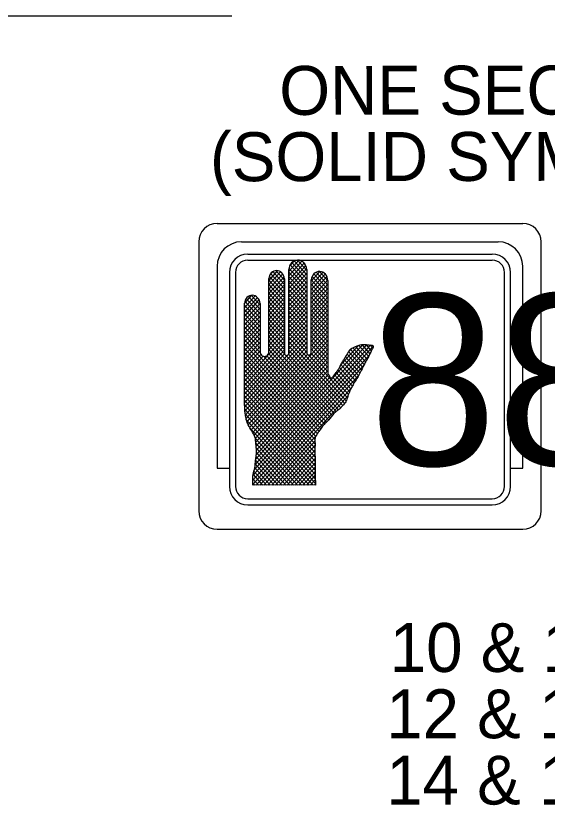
# Model space of a CAD drawing. Extents: x 1280742 to 1281742, y 1892348 to 1892988.
# Drawn here: x 1281004.7 to 1281048.2, y 1892503.7 to 1892568.2 of the extents above; entities that cross this region are included whole.
import ezdxf

# ---------------------------------------------------------------- set-up
doc = ezdxf.new("R2010")
doc.units = 0
doc.layers.add('T_Drafting', color=7, linetype='Continuous')
doc.layers.add('T_Notes', color=7, linetype='Continuous')

msp = doc.modelspace()

# ---------------------------------------------------------------- linework, layer by layer
at = {"layer": 'T_Drafting'}
for p, q in [((1281021.202, 1892551.259), (1281046.202, 1892551.259)), ((1281019.702, 1892549.759), (1281019.702, 1892527.759)), ((1281023.202, 1892549.759), (1281044.202, 1892549.759)), ((1281047.702, 1892527.759), (1281047.702, 1892549.759)), ((1281023.702, 1892548.759), (1281043.702, 1892548.759)), ((1281023.702, 1892548.259), (1281043.702, 1892548.259)), ((1281027.066, 1892547.343), (1281027.888, 1892548.256)), ((1281027.066, 1892546.99), (1281028.131, 1892548.173)), ((1281027.067, 1892546.637), (1281028.315, 1892548.024)), ((1281027.067, 1892546.283), (1281028.45, 1892547.82)), ((1281027.119, 1892547.756), (1281027.52, 1892548.202)), ((1281027.171, 1892547.871), (1281028.53, 1892546.361)), ((1281027.317, 1892548.062), (1281028.53, 1892546.715)), ((1281027.513, 1892548.198), (1281028.53, 1892547.069)), ((1281027.774, 1892548.262), (1281028.529, 1892547.423)), ((1281028.24, 1892548.097), (1281028.382, 1892547.939)), ((1281021.202, 1892547.759), (1281021.202, 1892531.259)), ((1281022.202, 1892547.259), (1281022.202, 1892529.759)), ((1281022.702, 1892547.259), (1281022.702, 1892529.759)), ((1281025.428, 1892546.583), (1281026.165, 1892547.402)), ((1281025.428, 1892546.23), (1281026.397, 1892547.307)), ((1281025.428, 1892545.877), (1281026.565, 1892547.14)), ((1281025.485, 1892547), (1281025.796, 1892547.346)), ((1281025.58, 1892547.164), (1281026.701, 1892545.918)), ((1281025.755, 1892547.323), (1281026.701, 1892546.272)), ((1281025.997, 1892547.408), (1281026.701, 1892546.626)), ((1281026.422, 1892547.289), (1281026.591, 1892547.101)), ((1281027.073, 1892540.658), (1281027.065, 1892547.485)), ((1281027.066, 1892547.281), (1281028.531, 1892545.653)), ((1281027.067, 1892545.93), (1281028.525, 1892547.55)), ((1281027.068, 1892545.577), (1281028.529, 1892547.201)), ((1281027.081, 1892547.617), (1281028.531, 1892546.007)), ((1281028.529, 1892547.504), (1281028.537, 1892540.726)), ((1281028.896, 1892546.548), (1281029.602, 1892547.332)), ((1281028.896, 1892546.195), (1281029.859, 1892547.264)), ((1281028.897, 1892545.842), (1281030.048, 1892547.121)), ((1281029.111, 1892547.13), (1281030.258, 1892545.855)), ((1281029.303, 1892547.27), (1281030.257, 1892546.209)), ((1281029.565, 1892547.332), (1281030.257, 1892546.563)), ((1281044.702, 1892529.759), (1281044.702, 1892547.259)), ((1281045.202, 1892529.759), (1281045.202, 1892547.259)), ((1281046.202, 1892531.259), (1281046.202, 1892547.759)), ((1281025.434, 1892540.786), (1281025.427, 1892546.751)), ((1281025.427, 1892546.626), (1281026.702, 1892545.21)), ((1281025.429, 1892545.524), (1281026.674, 1892546.908)), ((1281025.429, 1892545.171), (1281026.701, 1892546.584)), ((1281025.463, 1892546.94), (1281026.702, 1892545.564)), ((1281026.7, 1892546.737), (1281026.707, 1892540.691)), ((1281027.066, 1892546.927), (1281028.531, 1892545.299)), ((1281027.067, 1892546.573), (1281028.532, 1892544.945)), ((1281027.068, 1892545.224), (1281028.53, 1892546.848)), ((1281027.069, 1892544.871), (1281028.53, 1892546.495)), ((1281028.903, 1892540.694), (1281028.896, 1892546.642)), ((1281028.897, 1892545.489), (1281030.183, 1892546.918)), ((1281028.897, 1892546.66), (1281030.258, 1892545.148)), ((1281028.898, 1892545.135), (1281030.254, 1892546.643)), ((1281028.973, 1892546.93), (1281030.258, 1892545.501)), ((1281030.257, 1892546.595), (1281030.266, 1892538.938)), ((1281025.428, 1892546.272), (1281026.703, 1892544.856)), ((1281025.428, 1892545.918), (1281026.703, 1892544.502)), ((1281025.43, 1892544.818), (1281026.701, 1892546.231)), ((1281025.43, 1892544.465), (1281026.702, 1892545.877)), ((1281027.067, 1892546.219), (1281028.532, 1892544.591)), ((1281027.067, 1892545.865), (1281028.533, 1892544.237)), ((1281027.069, 1892544.518), (1281028.531, 1892546.142)), ((1281028.896, 1892546.307), (1281030.259, 1892544.794)), ((1281028.897, 1892545.953), (1281030.259, 1892544.44)), ((1281028.898, 1892544.782), (1281030.257, 1892546.293)), ((1281028.898, 1892544.429), (1281030.258, 1892545.94)), ((1281023.439, 1892544.728), (1281024.035, 1892545.389)), ((1281023.44, 1892544.374), (1281024.31, 1892545.341)), ((1281023.44, 1892544.021), (1281024.506, 1892545.205)), ((1281023.759, 1892545.298), (1281024.713, 1892544.238)), ((1281023.998, 1892545.386), (1281024.713, 1892544.592)), ((1281024.402, 1892545.291), (1281024.624, 1892545.044)), ((1281025.429, 1892545.564), (1281026.703, 1892544.148)), ((1281025.429, 1892545.21), (1281026.704, 1892543.794)), ((1281025.43, 1892544.111), (1281026.702, 1892545.524)), ((1281027.068, 1892545.511), (1281028.533, 1892543.883)), ((1281027.069, 1892544.165), (1281028.531, 1892545.789)), ((1281027.07, 1892543.812), (1281028.531, 1892545.436)), ((1281028.897, 1892545.599), (1281030.26, 1892544.086)), ((1281028.897, 1892545.245), (1281030.26, 1892543.732)), ((1281028.899, 1892544.076), (1281030.258, 1892545.586)), ((1281028.899, 1892543.723), (1281030.258, 1892545.233)), ((1281023.448, 1892536.487), (1281023.439, 1892544.73)), ((1281023.439, 1892544.592), (1281024.714, 1892543.176)), ((1281023.44, 1892543.668), (1281024.643, 1892545.005)), ((1281023.441, 1892543.315), (1281024.712, 1892544.727)), ((1281023.472, 1892544.91), (1281024.714, 1892543.53)), ((1281023.586, 1892545.137), (1281024.713, 1892543.884)), ((1281024.712, 1892544.716), (1281024.717, 1892540.785)), ((1281025.429, 1892544.856), (1281026.704, 1892543.44)), ((1281025.431, 1892543.758), (1281026.702, 1892545.171)), ((1281025.431, 1892543.405), (1281026.703, 1892544.818)), ((1281027.068, 1892545.157), (1281028.533, 1892543.529)), ((1281027.069, 1892544.803), (1281028.534, 1892543.175)), ((1281027.07, 1892543.459), (1281028.532, 1892545.083)), ((1281027.071, 1892543.105), (1281028.532, 1892544.729)), ((1281028.898, 1892544.891), (1281030.26, 1892543.378)), ((1281028.898, 1892544.537), (1281030.261, 1892543.024)), ((1281028.9, 1892543.37), (1281030.259, 1892544.88)), ((1281023.44, 1892544.238), (1281024.715, 1892542.822)), ((1281023.441, 1892542.962), (1281024.713, 1892544.375)), ((1281023.442, 1892542.609), (1281024.713, 1892544.022)), ((1281025.43, 1892544.502), (1281026.705, 1892543.086)), ((1281025.43, 1892544.148), (1281026.705, 1892542.732)), ((1281025.432, 1892543.052), (1281026.703, 1892544.465)), ((1281025.432, 1892542.699), (1281026.704, 1892544.112)), ((1281027.069, 1892544.449), (1281028.534, 1892542.821)), ((1281027.069, 1892544.095), (1281028.535, 1892542.467)), ((1281027.071, 1892542.752), (1281028.532, 1892544.376)), ((1281027.071, 1892542.399), (1281028.533, 1892544.023)), ((1281028.899, 1892544.183), (1281030.261, 1892542.67)), ((1281028.9, 1892543.017), (1281030.259, 1892544.527)), ((1281028.9, 1892542.664), (1281030.259, 1892544.174)), ((1281023.44, 1892543.884), (1281024.715, 1892542.468)), ((1281023.441, 1892543.53), (1281024.715, 1892542.114)), ((1281023.442, 1892542.256), (1281024.714, 1892543.669)), ((1281023.442, 1892541.903), (1281024.714, 1892543.316)), ((1281025.431, 1892543.794), (1281026.705, 1892542.378)), ((1281025.431, 1892543.44), (1281026.706, 1892542.024)), ((1281025.432, 1892542.346), (1281026.704, 1892543.759)), ((1281025.433, 1892541.993), (1281026.704, 1892543.406)), ((1281027.07, 1892543.741), (1281028.535, 1892542.113)), ((1281027.07, 1892543.387), (1281028.535, 1892541.759)), ((1281027.072, 1892542.046), (1281028.533, 1892543.67)), ((1281027.072, 1892541.693), (1281028.534, 1892543.317)), ((1281028.899, 1892543.829), (1281030.261, 1892542.316)), ((1281028.899, 1892543.475), (1281030.262, 1892541.962)), ((1281028.901, 1892542.311), (1281030.26, 1892543.821)), ((1281028.901, 1892541.958), (1281030.26, 1892543.467)), ((1281023.441, 1892543.176), (1281024.716, 1892541.76)), ((1281023.441, 1892542.822), (1281024.716, 1892541.406)), ((1281023.443, 1892541.549), (1281024.715, 1892542.963)), ((1281023.443, 1892541.196), (1281024.715, 1892542.609)), ((1281025.431, 1892543.086), (1281026.706, 1892541.67)), ((1281025.432, 1892542.732), (1281026.707, 1892541.316)), ((1281025.433, 1892541.64), (1281026.705, 1892543.053)), ((1281025.434, 1892541.287), (1281026.705, 1892542.699)), ((1281027.071, 1892543.033), (1281028.536, 1892541.405)), ((1281027.071, 1892542.679), (1281028.536, 1892541.051)), ((1281027.073, 1892541.34), (1281028.534, 1892542.964)), ((1281027.073, 1892540.987), (1281028.534, 1892542.611)), ((1281028.9, 1892543.121), (1281030.262, 1892541.608)), ((1281028.9, 1892542.767), (1281030.262, 1892541.254)), ((1281028.902, 1892541.604), (1281030.26, 1892543.114)), ((1281028.902, 1892541.251), (1281030.261, 1892542.761)), ((1281023.442, 1892542.469), (1281024.717, 1892541.052)), ((1281023.442, 1892542.115), (1281024.729, 1892540.685)), ((1281023.444, 1892540.843), (1281024.715, 1892542.256)), ((1281023.446, 1892538.371), (1281026.706, 1892541.993)), ((1281023.741, 1892534.81), (1281030.262, 1892542.055)), ((1281025.432, 1892542.378), (1281026.707, 1892540.962)), ((1281025.433, 1892542.024), (1281026.723, 1892540.59)), ((1281025.434, 1892540.933), (1281026.706, 1892542.346)), ((1281027.069, 1892540.629), (1281028.535, 1892542.258)), ((1281027.071, 1892542.325), (1281028.531, 1892540.703)), ((1281027.072, 1892541.971), (1281031.766, 1892536.755)), ((1281028.901, 1892542.413), (1281030.263, 1892540.9)), ((1281028.901, 1892542.06), (1281030.263, 1892540.546)), ((1281028.902, 1892540.898), (1281030.261, 1892542.408)), ((1281023.443, 1892541.761), (1281029.82, 1892534.674)), ((1281023.443, 1892541.407), (1281029.672, 1892534.485)), ((1281023.444, 1892540.49), (1281024.716, 1892541.903)), ((1281023.444, 1892540.137), (1281024.716, 1892541.55)), ((1281023.447, 1892538.018), (1281026.706, 1892541.64)), ((1281023.46, 1892536.266), (1281028.535, 1892541.904)), ((1281023.472, 1892535.925), (1281028.536, 1892541.551)), ((1281023.864, 1892534.593), (1281030.262, 1892541.702)), ((1281023.99, 1892534.379), (1281030.262, 1892541.349)), ((1281024.134, 1892530.651), (1281033.74, 1892541.323)), ((1281024.239, 1892531.121), (1281033.451, 1892541.356)), ((1281024.31, 1892531.553), (1281033.132, 1892541.356)), ((1281025.433, 1892541.67), (1281030.78, 1892535.73)), ((1281025.433, 1892541.316), (1281030.623, 1892535.55)), ((1281027.072, 1892541.617), (1281031.626, 1892536.557)), ((1281028.901, 1892541.706), (1281030.263, 1892540.192)), ((1281028.902, 1892541.352), (1281030.264, 1892539.838)), ((1281033.035, 1892541.355), (1281033.701, 1892540.615)), ((1281033.353, 1892541.356), (1281033.814, 1892540.843)), ((1281033.695, 1892541.33), (1281033.925, 1892541.074)), ((1281023.443, 1892541.053), (1281029.538, 1892534.28)), ((1281023.444, 1892540.699), (1281029.395, 1892534.086)), ((1281023.445, 1892539.784), (1281024.717, 1892541.197)), ((1281023.445, 1892539.431), (1281024.717, 1892540.844)), ((1281023.447, 1892537.665), (1281026.707, 1892541.287)), ((1281023.447, 1892537.312), (1281026.707, 1892540.934)), ((1281023.52, 1892535.625), (1281028.536, 1892541.198)), ((1281023.57, 1892535.326), (1281028.536, 1892540.845)), ((1281024.113, 1892534.163), (1281030.263, 1892540.995)), ((1281024.124, 1892530.286), (1281033.97, 1892541.226)), ((1281025.434, 1892540.962), (1281030.466, 1892535.37)), ((1281027.073, 1892541.263), (1281031.476, 1892536.37)), ((1281027.073, 1892540.909), (1281031.319, 1892536.19)), ((1281028.902, 1892540.998), (1281030.264, 1892539.484)), ((1281031.304, 1892539.677), (1281032.759, 1892541.294)), ((1281031.905, 1892540.699), (1281032.247, 1892541.079)), ((1281031.96, 1892540.782), (1281033.115, 1892539.499)), ((1281032.111, 1892540.968), (1281033.227, 1892539.728)), ((1281032.308, 1892541.102), (1281033.349, 1892539.945)), ((1281032.533, 1892541.206), (1281033.477, 1892540.157)), ((1281032.768, 1892541.298), (1281033.599, 1892540.375)), ((1281023.444, 1892540.345), (1281029.283, 1892533.857)), ((1281023.445, 1892539.078), (1281024.78, 1892540.56)), ((1281023.446, 1892538.724), (1281024.961, 1892540.408)), ((1281023.448, 1892536.959), (1281026.721, 1892540.596)), ((1281023.448, 1892536.606), (1281026.931, 1892540.475)), ((1281023.634, 1892535.044), (1281028.594, 1892540.556)), ((1281024.124, 1892529.932), (1281033.664, 1892540.532)), ((1281024.234, 1892533.944), (1281030.263, 1892540.642)), ((1281024.329, 1892533.695), (1281030.263, 1892540.289)), ((1281024.985, 1892540.4), (1281029.98, 1892534.851)), ((1281025.262, 1892540.446), (1281030.142, 1892535.024)), ((1281025.408, 1892540.637), (1281030.304, 1892535.197)), ((1281026.815, 1892540.488), (1281030.951, 1892535.893)), ((1281027.052, 1892540.578), (1281031.139, 1892536.037)), ((1281028.709, 1892540.505), (1281031.859, 1892537.005)), ((1281028.895, 1892540.652), (1281030.265, 1892539.13)), ((1281031.569, 1892540.156), (1281032.766, 1892538.825)), ((1281031.708, 1892540.355), (1281032.886, 1892539.046)), ((1281031.829, 1892540.574), (1281033.003, 1892539.27)), ((1281023.444, 1892539.991), (1281029.199, 1892533.596)), ((1281023.445, 1892539.637), (1281029.21, 1892533.231)), ((1281024.364, 1892533.381), (1281030.264, 1892539.936)), ((1281024.389, 1892529.873), (1281033.188, 1892539.649)), ((1281024.395, 1892533.061), (1281030.264, 1892539.583)), ((1281031.218, 1892539.485), (1281032.384, 1892538.19)), ((1281031.324, 1892539.721), (1281032.515, 1892538.397)), ((1281031.444, 1892539.941), (1281032.645, 1892538.607)), ((1281023.445, 1892539.283), (1281029.196, 1892532.893)), ((1281023.446, 1892538.929), (1281029.197, 1892532.539)), ((1281024.411, 1892532.372), (1281030.31, 1892538.927)), ((1281024.413, 1892532.728), (1281030.264, 1892539.23)), ((1281024.708, 1892529.874), (1281032.769, 1892538.831)), ((1281030.798, 1892538.891), (1281032.036, 1892537.516)), ((1281030.946, 1892539.08), (1281032.143, 1892537.75)), ((1281031.08, 1892539.285), (1281032.262, 1892537.971)), ((1281023.446, 1892538.575), (1281029.213, 1892532.167)), ((1281023.446, 1892538.221), (1281029.214, 1892531.812)), ((1281024.355, 1892531.956), (1281030.427, 1892538.703)), ((1281030.649, 1892538.703), (1281031.941, 1892537.267)), ((1281023.447, 1892537.867), (1281029.215, 1892531.458)), ((1281023.447, 1892537.513), (1281029.215, 1892531.104)), ((1281025.027, 1892529.874), (1281032.187, 1892537.83)), ((1281023.448, 1892537.159), (1281029.218, 1892530.748)), ((1281023.448, 1892536.805), (1281029.232, 1892530.378)), ((1281025.345, 1892529.875), (1281031.904, 1892537.162)), ((1281023.45, 1892536.449), (1281029.252, 1892530.003)), ((1281023.463, 1892536.081), (1281029.044, 1892529.88)), ((1281023.513, 1892535.672), (1281028.726, 1892529.879)), ((1281023.584, 1892535.239), (1281028.408, 1892529.879)), ((1281023.896, 1892534.539), (1281028.091, 1892529.879)), ((1281024.327, 1892533.707), (1281027.773, 1892529.878)), ((1281025.664, 1892529.875), (1281029.337, 1892533.956)), ((1281024.373, 1892533.303), (1281027.455, 1892529.878)), ((1281025.982, 1892529.876), (1281029.206, 1892533.457)), ((1281026.301, 1892529.876), (1281029.204, 1892533.101)), ((1281024.404, 1892532.914), (1281027.137, 1892529.877)), ((1281024.417, 1892532.547), (1281026.819, 1892529.877)), ((1281026.62, 1892529.877), (1281029.195, 1892532.738)), ((1281026.938, 1892529.877), (1281029.203, 1892532.393)), ((1281024.349, 1892531.914), (1281026.184, 1892529.876)), ((1281024.396, 1892532.216), (1281026.502, 1892529.876)), ((1281027.257, 1892529.877), (1281029.214, 1892532.052)), ((1281027.575, 1892529.878), (1281029.215, 1892531.699)), ((1281021.202, 1892531.259), (1281022.202, 1892531.259)), ((1281024.204, 1892531.015), (1281025.23, 1892529.875)), ((1281024.279, 1892531.285), (1281025.548, 1892529.875)), ((1281024.314, 1892531.599), (1281025.866, 1892529.875)), ((1281027.894, 1892529.878), (1281029.215, 1892531.346)), ((1281028.213, 1892529.879), (1281029.215, 1892530.993)), ((1281045.202, 1892531.259), (1281046.202, 1892531.259)), ((1281024.125, 1892530.395), (1281024.595, 1892529.874)), ((1281024.14, 1892530.733), (1281024.913, 1892529.874)), ((1281028.531, 1892529.879), (1281029.221, 1892530.645)), ((1281024.124, 1892530.043), (1281024.277, 1892529.873)), ((1281024.15, 1892529.873), (1281024.124, 1892529.905)), ((1281029.229, 1892529.88), (1281024.15, 1892529.873)), ((1281028.85, 1892529.88), (1281029.235, 1892530.308)), ((1281029.168, 1892529.88), (1281029.252, 1892529.973)), ((1281029.253, 1892529.874), (1281029.229, 1892529.88)), ((1281023.702, 1892528.759), (1281043.702, 1892528.759)), ((1281023.702, 1892528.259), (1281043.702, 1892528.259)), ((1281021.202, 1892526.259), (1281046.202, 1892526.259))]:
    msp.add_line(p, q, dxfattribs=at)
for centre, radius, start, end in [((1281021.202, 1892549.759), 1.5, 90, 180), ((1281046.202, 1892549.759), 1.5, 0, 90), ((1281023.202, 1892547.759), 2, 90, 180), ((1281044.202, 1892547.759), 2, 0, 90), ((1281023.702, 1892547.259), 1.5, 90, 180), ((1281043.702, 1892547.259), 1.5, 0, 90), ((1281023.702, 1892547.259), 1, 90, 180), ((1281043.702, 1892547.259), 1, 0, 90), ((1281023.702, 1892529.759), 1.5, 180, 270), ((1281023.702, 1892529.759), 1, 180, 270), ((1281043.702, 1892529.759), 1.5, 270, 0), ((1281043.702, 1892529.759), 1, 270, 0), ((1281021.202, 1892527.759), 1.5, 180, 270), ((1281046.202, 1892527.759), 1.5, 270, 0)]:
    msp.add_arc(centre, radius, start, end, dxfattribs=at)
for centre, major_axis, start_param, end_param in [((1281027.798, 1892547.448), (0, -0.814), 1.640121, 4.665593), ((1281026.064, 1892546.703), (0, -0.709), 1.618611, 4.644084), ((1281029.575, 1892546.575), (0, -0.758), 1.597842, 4.623315), ((1281024.076, 1892544.682), (0, -0.709), 1.618611, 4.644084), ((1281025.076, 1892540.786), (0, -0.398), 4.713646, 7.855239), ((1281026.89, 1892540.674), (0, -0.204), 4.633755, 7.775348), ((1281028.717, 1892540.711), (0, -0.207), 4.624552, 7.766145)]:
    msp.add_ellipse(centre, major_axis=major_axis, ratio=0.9, start_param=start_param, end_param=end_param, dxfattribs=at)
for points in [[(1281030.265, 1892538.939), (1281030.316, 1892538.925), (1281030.386, 1892538.77), (1281030.474, 1892538.651), (1281030.526, 1892538.632), (1281030.613, 1892538.651), (1281030.667, 1892538.731), (1281030.825, 1892538.925), (1281030.949, 1892539.084), (1281031.019, 1892539.2), (1281031.089, 1892539.298), (1281031.212, 1892539.474), (1281031.282, 1892539.631), (1281031.387, 1892539.845), (1281031.458, 1892539.963), (1281031.581, 1892540.177), (1281031.72, 1892540.375), (1281031.826, 1892540.57), (1281031.948, 1892540.765), (1281032.055, 1892540.902), (1281032.212, 1892541.059), (1281032.405, 1892541.139), (1281032.511, 1892541.198), (1281032.67, 1892541.255), (1281032.81, 1892541.315), (1281033.022, 1892541.355), (1281033.198, 1892541.356), (1281033.426, 1892541.356), (1281033.638, 1892541.336), (1281033.884, 1892541.298), (1281033.954, 1892541.257), (1281033.97, 1892541.2), (1281033.867, 1892540.946), (1281033.796, 1892540.808), (1281033.727, 1892540.669), (1281033.656, 1892540.514), (1281033.62, 1892540.416), (1281033.48, 1892540.161), (1281033.271, 1892539.81), (1281032.989, 1892539.242), (1281032.638, 1892538.595), (1281032.357, 1892538.145), (1281032.198, 1892537.851), (1281032.059, 1892537.576), (1281031.977, 1892537.359), (1281031.933, 1892537.248), (1281031.777, 1892536.776), (1281031.532, 1892536.442), (1281031.338, 1892536.208), (1281031.057, 1892535.972), (1281030.881, 1892535.834), (1281030.425, 1892535.325), (1281030.021, 1892534.895), (1281029.758, 1892534.601), (1281029.528, 1892534.267), (1281029.414, 1892534.121), (1281029.318, 1892533.916), (1281029.212, 1892533.719), (1281029.213, 1892533.289), (1281029.196, 1892532.903), (1281029.196, 1892532.549), (1281029.214, 1892532.081), (1281029.215, 1892531.631), (1281029.215, 1892530.907), (1281029.234, 1892530.324), (1281029.251, 1892530.108), (1281029.252, 1892529.95), (1281029.252, 1892529.875)], [(1281024.124, 1892529.905), (1281024.124, 1892530.219), (1281024.141, 1892530.746), (1281024.28, 1892531.294), (1281024.35, 1892531.92), (1281024.403, 1892532.272), (1281024.402, 1892532.957), (1281024.348, 1892533.524), (1281024.295, 1892533.817), (1281024.031, 1892534.306), (1281023.749, 1892534.796), (1281023.59, 1892535.206), (1281023.519, 1892535.636), (1281023.465, 1892535.969), (1281023.465, 1892536.183), (1281023.448, 1892536.487)]]:
    msp.add_spline(points, degree=3, dxfattribs=at)
at = {"layer": 'T_Notes'}
msp.add_line((1280924.224, 1892568.237), (1281022.409, 1892568.237), dxfattribs=at)

# ---------------------------------------------------------------- texts
at = {"layer": 'T_Drafting'}
for s, height, p in [('ONE SECTION', 4, (1281026.287, 1892560.136)), ('(SOLID SYMBOL)', 4, (1281020.622, 1892554.711)), ('88', 14, (1281033.666, 1892531.48))]:
    msp.add_text(s, height=height, rotation=0.07203, dxfattribs=at).set_placement(p)
at = {"layer": 'T_Notes'}
for s, p in [('10 & 11', (1281035.325, 1892514.597)), ('12 & 13', (1281035.033, 1892509.178)), ('14 & 15', (1281035.034, 1892503.76))]:
    msp.add_text(s, height=4, dxfattribs=at).set_placement(p)

doc.saveas('drawing.dxf')
